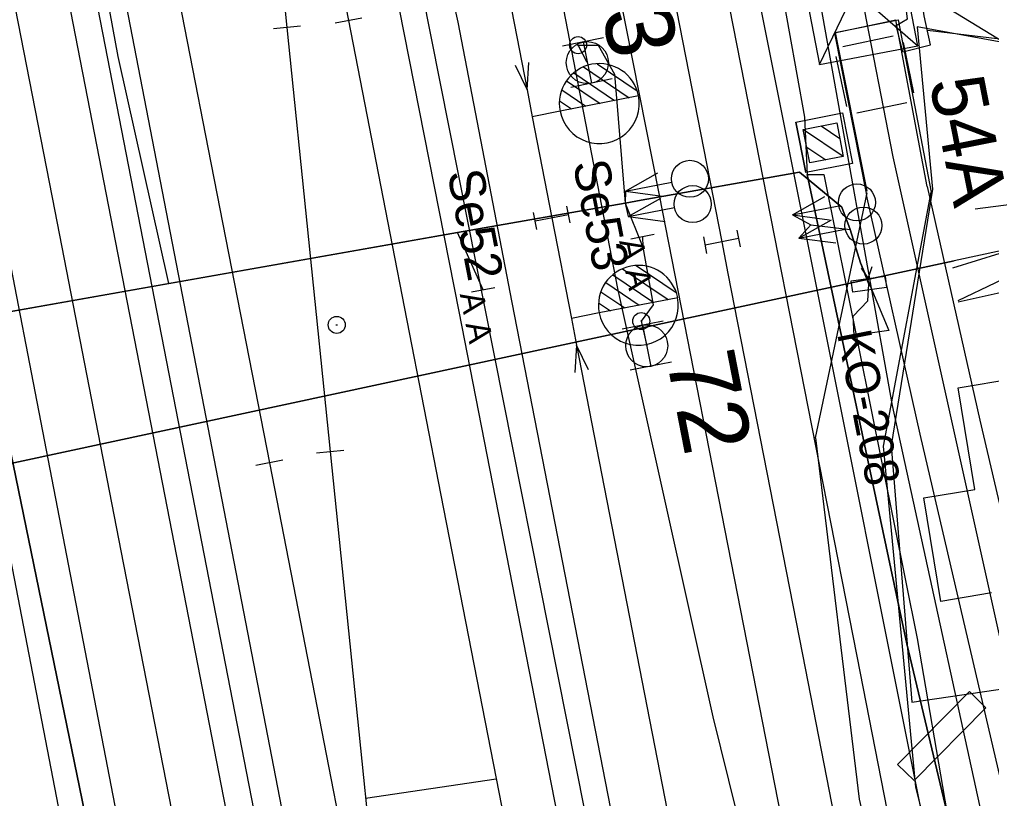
# Model space of a CAD drawing. Extents: x -545736 to -544888, y -1122892 to -1119128.
# Drawn here: x -545268.13 to -545239.66, y -1121503.39 to -1121480.58 of the extents above; entities that cross this region are included whole.
import ezdxf

# ---------------------------------------------------------------- set-up
doc = ezdxf.new("R2010")
doc.units = 0
for name, color, linetype in [('osvětlené plochy-hodnota-obrys', 7, 'Continuous'), ('Vrstva 1 - Koleje', 7, 'Continuous'), ('Vrstva 11 - Trakce', 7, 'Continuous'), ('Vrstva 12 - Trakce zaklady', 7, 'Continuous'), ('Vrstva 16', 7, 'Continuous'), ('Vrstva 16_plochy', 7, 'Continuous'), ('Vrstva 17', 7, 'Continuous'), ('Vrstva 2 - Vyhybky', 7, 'Continuous'), ('Vrstva 23 - PHS - pozemni - schody - eskalatory', 7, 'Continuous'), ('Vrstva 26', 7, 'Continuous'), ('Vrstva 27', 7, 'Continuous'), ('Vrstva 28', 7, 'Continuous'), ('Vrstva 28 - zabzar', 7, 'Continuous'), ('Vrstva 3 - Lisy - Pocitaci body', 7, 'Continuous'), ('Vrstva 31', 7, 'Continuous'), ('Vrstva 33 - prvky sdelzar', 7, 'Continuous'), ('Vrstva 34', 7, 'Continuous'), ('Vrstva 35', 7, 'Continuous'), ('Vrstva 4 - Teren - stezky - prechody - plochy', 7, 'Continuous'), ('Vrstva 44', 7, 'Continuous'), ('Vrstva 49', 7, 'Continuous'), ('Vrstva 51', 7, 'Continuous'), ('Vrstva 6 - Navesti', 7, 'Continuous'), ('Vrstva 63', 7, 'Continuous'), ('Vrstva 7 - Namezniky-vystroj', 7, 'Continuous')]:
    doc.layers.add(name, color=color, linetype=linetype)

msp = doc.modelspace()

# ---------------------------------------------------------------- linework, layer by layer
at = {"layer": 'osvětlené plochy-hodnota-obrys'}
for points in [[(-545242.558, -1121491.884), (-545279.836, -1121284), (-545274.806, -1121164.44), (-545297.02, -1121162.185), (-545335.871, -1121169.76), (-545274.177, -1121498.125)], [(-545225.649, -1121565.547), (-545228.661, -1121555.541), (-545242.558, -1121491.884)]]:
    msp.add_lwpolyline(points, dxfattribs=at)
at = {"layer": 'Vrstva 1 - Koleje'}
for points in [[(-545262.507, -1121410.398), (-545262.372, -1121411.093), (-545261.803, -1121414.016), (-545261.166, -1121417.289), (-545259.554, -1121425.557), (-545257.889, -1121434.106), (-545256.293, -1121442.3), (-545253.813, -1121455.021), (-545252.192, -1121463.347), (-545250.579, -1121471.624), (-545249.065, -1121479.401), (-545247.561, -1121487.089), (-545247.38, -1121488.014), (-545245.2, -1121499.168), (-545243.649, -1121507.124), (-545242.128, -1121514.923), (-545240.701, -1121522.235), (-545239.742, -1121527.165), (-545236.674, -1121542.917), (-545232.9, -1121554.103), (-545232.644, -1121554.861)], [(-545271.831, -1121412.223), (-545270.376, -1121419.688), (-545264.77, -1121438.968), (-545261.284, -1121450.925), (-545255.713, -1121470.07), (-545253.264, -1121482.64), (-545253.111, -1121483.425)], [(-545276.49, -1121413.135), (-545275.337, -1121419.059), (-545273.775, -1121427.064), (-545272.315, -1121434.562), (-545270.926, -1121441.685), (-545269.354, -1121449.751), (-545267.851, -1121457.452), (-545267.665, -1121458.407), (-545265.736, -1121468.305), (-545264.214, -1121476.109), (-545262.603, -1121484.378), (-545260.81, -1121493.562), (-545256.987, -1121513.182), (-545255.196, -1121522.374), (-545254.536, -1121525.758), (-545254.381, -1121526.553)], [(-545262.934, -1121433.025), (-545261.614, -1121439.792), (-545259.539, -1121450.431), (-545255.713, -1121470.07), (-545253.264, -1121482.64), (-545253.111, -1121483.425)], [(-545264.923, -1121447.662), (-545264.772, -1121448.437), (-545262.317, -1121461.012), (-545258.493, -1121480.612), (-545257.28, -1121486.838), (-545255.786, -1121494.509), (-545254.093, -1121503.208), (-545252.404, -1121511.864), (-545250.837, -1121519.906), (-545249.341, -1121527.573), (-545248.751, -1121530.6), (-545248.408, -1121532.36)], [(-545264.923, -1121447.662), (-545264.772, -1121448.437), (-545262.317, -1121461.012), (-545260.294, -1121480.812), (-545259.029, -1121493.226), (-545256.987, -1121513.182), (-545255.196, -1121522.374), (-545254.536, -1121525.758), (-545254.381, -1121526.553)], [(-545272.358, -1121459.202), (-545270.418, -1121469.16), (-545268.418, -1121479.39), (-545267.096, -1121486.195), (-545265.156, -1121496.137), (-545263.098, -1121506.678), (-545261.272, -1121516.035), (-545259.394, -1121525.622), (-545257.684, -1121534.921), (-545257.618, -1121535.277), (-545256.11, -1121545.231), (-545255.449, -1121550.493), (-545254.843, -1121556.163), (-545254.458, -1121560.418), (-545254.146, -1121564.071), (-545253.508, -1121571.471), (-545252.196, -1121587.434), (-545249.323, -1121602.182), (-545249.218, -1121602.722)], [(-545253.111, -1121483.425), (-545252.538, -1121486.383), (-545251.966, -1121489.333)], [(-545251.966, -1121489.333), (-545251.813, -1121490.118), (-545248.787, -1121505.64), (-545243.798, -1121521.586), (-545241.757, -1121527.849), (-545236.674, -1121542.917), (-545232.9, -1121554.103), (-545232.644, -1121554.861)], [(-545251.966, -1121489.333), (-545251.813, -1121490.118), (-545248.787, -1121505.64), (-545245.606, -1121521.941), (-545243.747, -1121531.464)]]:
    msp.add_lwpolyline(points, dxfattribs=at)
at = {"layer": 'Vrstva 11 - Trakce'}
for p, q in [((-545245.172, -1121483.799), (-545244.001, -1121484.584)), ((-545244.653, -1121483.696), (-545244.104, -1121484.064)), ((-545245.073, -1121484.316), (-545244.518, -1121484.689))]:
    msp.add_line(p, q, dxfattribs=at)
msp.add_lwpolyline([(-545244.194, -1121483.606), (-545244.001, -1121484.587), (-545244.982, -1121484.78), (-545245.175, -1121483.799)], close=True, dxfattribs=at)
at = {"layer": 'Vrstva 12 - Trakce zaklady'}
for p, q in [((-545245.396, -1121483.585), (-545244.023, -1121483.314)), ((-545243.731, -1121484.792), (-545245.104, -1121485.063))]:
    msp.add_line(p, q, dxfattribs=at)
for points in [[(-545245.104, -1121485.063), (-545245.396, -1121483.585), (-545244.023, -1121483.314), (-545243.731, -1121484.792), (-545245.104, -1121485.063)], [(-545244.023, -1121483.314), (-545244.023, -1121483.314), (-545243.731, -1121484.792), (-545243.731, -1121484.792)], [(-545245.396, -1121483.585), (-545245.396, -1121483.585), (-545245.104, -1121485.063), (-545245.104, -1121485.063)]]:
    msp.add_lwpolyline(points, dxfattribs=at)
at = {"layer": 'Vrstva 16'}
for p, q in [((-545244.819, -1121492.83), (-545243.304, -1121485.657)), ((-545242.827, -1121493.072), (-545241.429, -1121485.638))]:
    msp.add_line(p, q, dxfattribs=at)
for points in [[(-545244.819, -1121492.83), (-545243.535, -1121503.405), (-545242.594, -1121507.523), (-545242.146, -1121508.542), (-545236.367, -1121515.605), (-545236.148, -1121516.062)], [(-545234.51, -1121515.366), (-545235.05, -1121514.456), (-545240.697, -1121507.522), (-545240.867, -1121507.078), (-545241.875, -1121503.055), (-545242.827, -1121493.072)]]:
    msp.add_lwpolyline(points, dxfattribs=at)
at = {"layer": 'Vrstva 16_plochy'}
msp.add_line((-545242.256, -1121481.525), (-545242.453, -1121480.759), dxfattribs=at)
for points in [[(-545242.453, -1121480.759), (-545242.124, -1121480.556), (-545242.465, -1121477.85), (-545241.84, -1121477.607), (-545242.071, -1121476.407), (-545246.05, -1121477.203), (-545246.055, -1121477.191), (-545246.306, -1121476.097), (-545247.276, -1121471.24), (-545242.26, -1121473.137)], [(-545242.256, -1121481.525), (-545241.45, -1121481.321), (-545241.63, -1121480.47), (-545241.966, -1121478.12), (-545241.235, -1121477.966), (-545241.565, -1121476.301), (-545241.813, -1121475.513)]]:
    msp.add_lwpolyline(points, dxfattribs=at)
at = {"layer": 'Vrstva 17'}
msp.add_line((-545239.108, -1121481.368), (-545247.14, -1121476.462), dxfattribs=at)
at = {"layer": 'Vrstva 2 - Vyhybky'}
for p, q in [((-545258.1, -1121480.536), (-545258.886, -1121480.688)), ((-545259.896, -1121480.771), (-545260.692, -1121480.853)), ((-545251.215, -1121481.873), (-545250.04, -1121482.664)), ((-545251.898, -1121482.145), (-545250.699, -1121482.953)), ((-545251.615, -1121481.969), (-545250.277, -1121482.871)), ((-545252.105, -1121482.372), (-545251.122, -1121483.036)), ((-545249.997, -1121482.816), (-545252.296, -1121483.264)), ((-545252.246, -1121482.643), (-545251.543, -1121483.117)), ((-545249.997, -1121482.816), (-545249.997, -1121482.816)), ((-545252.313, -1121482.965), (-545251.966, -1121483.199)), ((-545252.295, -1121483.264), (-545253.111, -1121483.425)), ((-545250.468, -1121487.879), (-545249.132, -1121488.782)), ((-545250.068, -1121487.782), (-545248.894, -1121488.575)), ((-545250.752, -1121488.054), (-545249.554, -1121488.863)), ((-545250.959, -1121488.281), (-545249.976, -1121488.945)), ((-545248.852, -1121488.727), (-545251.15, -1121489.172)), ((-545251.1, -1121488.552), (-545250.398, -1121489.026)), ((-545248.852, -1121488.726), (-545248.852, -1121488.727)), ((-545251.168, -1121488.874), (-545250.821, -1121489.108)), ((-545251.15, -1121489.172), (-545251.966, -1121489.333)), ((-545259.427, -1121493.267), (-545258.631, -1121493.185)), ((-545260.417, -1121493.485), (-545261.203, -1121493.639))]:
    msp.add_line(p, q, dxfattribs=at)
for points in [[(-545264.923, -1121447.662), (-545264.772, -1121448.437), (-545262.317, -1121461.012), (-545258.493, -1121480.612)], [(-545259.539, -1121450.431), (-545255.713, -1121470.07), (-545253.264, -1121482.64), (-545253.111, -1121483.425)], [(-545262.317, -1121461.012), (-545260.294, -1121480.812)], [(-545253.615, -1121481.921), (-545253.264, -1121482.64), (-545253.209, -1121481.842)], [(-545251.966, -1121489.333), (-545251.813, -1121490.118), (-545248.787, -1121505.64), (-545245.606, -1121521.941)], [(-545251.462, -1121490.837), (-545251.813, -1121490.118), (-545251.868, -1121490.916)], [(-545259.029, -1121493.226), (-545256.987, -1121513.182)], [(-545260.81, -1121493.562), (-545256.987, -1121513.182), (-545254.536, -1121525.758), (-545254.381, -1121526.553)]]:
    msp.add_lwpolyline(points, dxfattribs=at)
for centre, radius, start, end in [((-545251.147, -1121483.04), 1.171, 11.0499, 191.0108), ((-545251.147, -1121483.041), 1.17, 190.9604, 11.4299), ((-545250.002, -1121488.95), 1.171, 10.9996, 190.9604), ((-545250.002, -1121488.951), 1.17, 190.91, 11.3796)]:
    msp.add_arc(centre, radius, start, end, dxfattribs=at)
at = {"layer": 'Vrstva 23 - PHS - pozemni - schody - eskalatory'}
msp.add_lwpolyline([(-545239.825, -1121500.735), (-545240.306, -1121500.26), (-545242.411, -1121502.392), (-545241.931, -1121502.867)], close=True, dxfattribs=at)
at = {"layer": 'Vrstva 26'}
for points in [[(-545097.437, -1122052.623), (-545072.287, -1122039.894), (-545085.621, -1122009.744), (-545089.841, -1121964.946), (-545095.239, -1121958.274), (-545095.745, -1121940.272), (-545098.424, -1121935.947), (-545099.088, -1121910.293), (-545099.581, -1121891.247), (-545095.82, -1121860.673), (-545104.239, -1121857.434), (-545113.591, -1121811.167), (-545113.924, -1121803.223), (-545124.359, -1121753.762), (-545132.104, -1121728.782), (-545141.308, -1121704.806), (-545150.282, -1121669.65), (-545151.919, -1121656.143), (-545151.404, -1121636.531), (-545180.167, -1121637.447), (-545212.798, -1121581.796), (-545235.977, -1121514.184), (-545242.54, -1121484.599), (-545257.211, -1121409.362)], [(-545240.793, -1121487.85), (-545238.719, -1121487.203), (-545240.754, -1121487.641), (-545273.299, -1121494.637), (-545275.897, -1121495.196), (-545278.827, -1121494.413), (-545280.156, -1121493.901), (-545287.156, -1121495.163), (-545287.928, -1121496.789), (-545287, -1121503.852)], [(-545273.299, -1121494.637), (-545240.754, -1121487.641)]]:
    msp.add_lwpolyline(points, dxfattribs=at)
at = {"layer": 'Vrstva 27'}
for p, q in [((-545251.758, -1121481.352), (-545251.782, -1121481.308)), ((-545243.767, -1121488.235), (-545243.765, -1121488.231)), ((-545249.925, -1121489.386), (-545249.915, -1121489.434))]:
    msp.add_line(p, q, dxfattribs=at)
msp.add_lwpolyline([(-545243.482, -1121487.857), (-545243.272, -1121488.165), (-545243.152, -1121487.812)], dxfattribs=at)
msp.add_lwpolyline([(-545243.768, -1121488.232), (-545242.777, -1121488.098), (-545242.732, -1121488.428), (-545243.723, -1121488.562)], close=True, dxfattribs=at)
for centre in [(-545251.77, -1121481.33), (-545249.92, -1121489.41)]:
    msp.add_circle(centre, 0.25, dxfattribs=at)
at = {"layer": 'Vrstva 28'}
msp.add_line((-545258.863, -1121489.522), (-545258.813, -1121489.522), dxfattribs=at)
msp.add_circle((-545258.838, -1121489.522), 0.25, dxfattribs=at)
at = {"layer": 'Vrstva 28 - zabzar'}
for p, q in [((-545244.95, -1121486.59), (-545243.8, -1121486.73)), ((-545254.55, -1121488.49), (-545255.296, -1121486.818)), ((-545249.88, -1121486.93), (-545249.87, -1121487.25))]:
    msp.add_line(p, q, dxfattribs=at)
for points in [[(-545263.754, -1121488.311), (-545265.24, -1121481.66), (-545267.32, -1121470.35), (-545269.76, -1121459.69), (-545270.37, -1121458.69), (-545270.17, -1121457.49)], [(-545251.5, -1121481.84), (-545251.77, -1121481.33), (-545251.18, -1121481.33), (-545250.7, -1121482.18), (-545250.391, -1121485.953)], [(-545260.9, -1121532.21), (-545262.64, -1121521.21), (-545269.213, -1121489.275), (-545263.754, -1121488.311), (-545255.296, -1121486.818), (-545250.391, -1121485.953), (-545249.918, -1121485.869), (-545245.288, -1121485.052)], [(-545242.67, -1121489.69), (-545243.68, -1121489.83), (-545243.71, -1121489.27), (-545243.28, -1121488.82), (-545243.25, -1121488.33), (-545243.5, -1121487.7), (-545243.8, -1121486.73), (-545244.04, -1121486.07), (-545245.288, -1121485.052)], [(-545250.38, -1121485.61), (-545250.391, -1121485.953), (-545250.3, -1121486.35)], [(-545250.391, -1121485.953), (-545249.87, -1121487.25), (-545249.57, -1121488.93), (-545249.92, -1121489.41), (-545249.76, -1121490.13)], [(-545245.49, -1121486.3), (-545244.95, -1121486.59), (-545245.3, -1121486.98)]]:
    msp.add_lwpolyline(points, dxfattribs=at)
at = {"layer": 'Vrstva 3 - Lisy - Pocitaci body'}
for p, q in [((-545251.02, -1121481.113), (-545252.227, -1121481.36)), ((-545251.623, -1121481.236), (-545251.377, -1121482.444)), ((-545250.773, -1121482.32), (-545251.98, -1121482.567)), ((-545250.38, -1121485.61), (-545249.43, -1121485.073)), ((-545250.38, -1121485.61), (-545249.026, -1121485.346)), ((-545250.38, -1121485.61), (-545249.298, -1121485.75)), ((-545250.3, -1121486.35), (-545249.35, -1121485.813)), ((-545245.49, -1121486.3), (-545244.54, -1121485.764)), ((-545252.981, -1121486.724), (-545253.076, -1121486.233)), ((-545252, -1121486.533), (-545252.095, -1121486.042)), ((-545250.3, -1121486.35), (-545248.946, -1121486.086)), ((-545245.49, -1121486.3), (-545244.135, -1121486.036)), ((-545253.029, -1121486.478), (-545252.047, -1121486.288)), ((-545250.3, -1121486.35), (-545249.218, -1121486.49)), ((-545245.49, -1121486.3), (-545244.408, -1121486.441)), ((-545245.3, -1121486.98), (-545244.35, -1121486.443)), ((-545247.118, -1121486.748), (-545247.022, -1121487.238)), ((-545245.3, -1121486.98), (-545243.946, -1121486.716)), ((-545248.1, -1121486.94), (-545248.004, -1121487.43)), ((-545247.07, -1121486.993), (-545248.052, -1121487.185)), ((-545245.3, -1121486.98), (-545244.218, -1121487.12)), ((-545249.273, -1121489.408), (-545250.482, -1121489.643)), ((-545249.878, -1121489.525), (-545249.642, -1121490.735)), ((-545249.038, -1121490.617), (-545250.247, -1121490.852))]:
    msp.add_line(p, q, dxfattribs=at)
for centre, radius in [((-545251.499, -1121481.842), 0.616), ((-545248.493, -1121485.244), 0.542), ((-545248.413, -1121485.984), 0.542), ((-545243.603, -1121485.935), 0.542), ((-545243.413, -1121486.614), 0.542), ((-545249.759, -1121490.132), 0.616)]:
    msp.add_circle(centre, radius, dxfattribs=at)
at = {"layer": 'Vrstva 31'}
for points in [[(-545245.288, -1121485.052), (-545249.918, -1121485.869), (-545250.391, -1121485.953), (-545255.296, -1121486.818), (-545269.213, -1121489.275), (-545274.17, -1121490.15), (-545276.21, -1121490.53), (-545277.51, -1121491.23), (-545280.09, -1121493.53), (-545282.98, -1121493.96), (-545287.42, -1121494.9), (-545288.26, -1121496.38), (-545287.72, -1121499.81), (-545286.73, -1121504.29), (-545285.98, -1121506.49), (-545286.39, -1121506.56)], [(-545245.288, -1121485.052), (-545249.918, -1121485.869), (-545250.391, -1121485.953), (-545255.296, -1121486.818), (-545269.213, -1121489.275), (-545262.64, -1121521.21), (-545260.84, -1121532.54), (-545266.43, -1121533.83), (-545268.66, -1121534.19), (-545269.96, -1121534.64), (-545265.7, -1121552.63), (-545264.92, -1121556.08), (-545263.22, -1121565.23), (-545260.72, -1121578.26), (-545257.95, -1121591.89), (-545254.58, -1121607.83), (-545254.47, -1121613.22), (-545255.28, -1121613.53), (-545259.51, -1121614.69), (-545260.17, -1121614.97), (-545261.24, -1121612.78), (-545262.15, -1121612.31), (-545262.45, -1121611.58)], [(-545245.288, -1121485.052), (-545244.04, -1121486.07), (-545243.8, -1121486.73), (-545243.5, -1121487.7), (-545242.67, -1121489.69)], [(-545245.288, -1121485.052), (-545244.04, -1121486.07), (-545243.8, -1121486.73), (-545243.5, -1121487.7), (-545242.67, -1121489.69)], [(-545240.638, -1121488.806), (-545238.428, -1121487.752), (-545227.164, -1121492.751), (-545226.347, -1121492.096)], [(-545226.347, -1121492.096), (-545227.164, -1121492.801), (-545238.177, -1121488.314), (-545240.638, -1121488.856)]]:
    msp.add_lwpolyline(points, dxfattribs=at)
at = {"layer": 'Vrstva 33 - prvky sdelzar'}
msp.add_lwpolyline([(-545245.288, -1121485.052), (-545249.918, -1121485.869), (-545250.391, -1121485.953), (-545255.296, -1121486.818), (-545269.213, -1121489.275), (-545274.17, -1121490.15)], dxfattribs=at)
at = {"layer": 'Vrstva 34'}
for p, q in [((-545244.013, -1121481.367), (-545242.545, -1121481.061)), ((-545242.249, -1121481.255), (-545241.943, -1121482.723)), ((-545243.901, -1121483.131), (-545244.207, -1121481.663)), ((-545242.137, -1121483.019), (-545243.605, -1121483.325))]:
    msp.add_line(p, q, dxfattribs=at)
for points in [[(-545243.668, -1121479.739), (-545241.819, -1121481.355), (-545253.781, -1121419.374), (-545254.848, -1121421.672), (-545256.694, -1121419.914), (-545244.697, -1121481.898), (-545241.819, -1121481.355)], [(-545244.697, -1121481.898), (-545243.668, -1121479.739), (-545254.848, -1121421.672)]]:
    msp.add_lwpolyline(points, dxfattribs=at)
at = {"layer": 'Vrstva 35'}
msp.add_line((-545269.213, -1121489.275), (-545263.754, -1121488.311), dxfattribs=at)
for points in [[(-545242.463, -1121480.602), (-545244.257, -1121480.975), (-545243.32, -1121485.713)], [(-545241.541, -1121485.465), (-545242.463, -1121480.602)], [(-545263.754, -1121488.311), (-545255.296, -1121486.818), (-545250.391, -1121485.953), (-545249.918, -1121485.869), (-545245.288, -1121485.052)], [(-545241.541, -1121485.465), (-545239.999, -1121492.308), (-545237.251, -1121504.071), (-545235.337, -1121513.168), (-545234.596, -1121515.041), (-545224.398, -1121544.845), (-545211.981, -1121581.286), (-545198.438, -1121604.211), (-545181.421, -1121633.25), (-545182.966, -1121634.194), (-545200.042, -1121605.172), (-545213.729, -1121581.837), (-545226.104, -1121545.417), (-545236.204, -1121516.019), (-545237.061, -1121513.796), (-545239.019, -1121504.439), (-545241.749, -1121492.723), (-545243.32, -1121485.713)]]:
    msp.add_lwpolyline(points, dxfattribs=at)
at = {"layer": 'Vrstva 4 - Teren - stezky - prechody - plochy'}
for points in [[(-545259.454, -1121409.801), (-545256.779, -1121423.634), (-545256.524, -1121424.828), (-545256.645, -1121424.859), (-545246.388, -1121477.246), (-545246.041, -1121478.436), (-545245.134, -1121483.441), (-545245.058, -1121485.118), (-545242.142, -1121498.86), (-545240.965, -1121503.781), (-545240.592, -1121505.558), (-545236.724, -1121527.376), (-545236.317, -1121528.858), (-545234.837, -1121535.705), (-545233.269, -1121542.92), (-545231.754, -1121547.059), (-545231.433, -1121548.349)], [(-545261.031, -1121410.109), (-545252.885, -1121451.66), (-545247.894, -1121477.411), (-545243.606, -1121499.217), (-545237.682, -1121529.497), (-545236.332, -1121535.818), (-545234.439, -1121543.527)], [(-545244.448, -1121510.946), (-545249.383, -1121485.722), (-545256.971, -1121447.411), (-545260.809, -1121427.087), (-545263.937, -1121410.678)], [(-545244.448, -1121510.946), (-545245.318, -1121511.096), (-545247.814, -1121501), (-545250.603, -1121488.46), (-545258.764, -1121446.291), (-545261.879, -1121430.313), (-545263.872, -1121418.434), (-545264.945, -1121410.876)], [(-545278.006, -1121413.432), (-545276.701, -1121420.101), (-545267.383, -1121467.848), (-545259.234, -1121509.979), (-545254.666, -1121533.136), (-545253.23, -1121541.319), (-545251.944, -1121549.565), (-545250.687, -1121560.647), (-545249.635, -1121574.047), (-545248.988, -1121585.208), (-545248.342, -1121594.545), (-545249.227, -1121594.662)], [(-545279.681, -1121413.76), (-545278.377, -1121420.495), (-545269.048, -1121467.98), (-545260.773, -1121510.451), (-545257.559, -1121527.04), (-545255.905, -1121536.357), (-545255.137, -1121541.48), (-545254, -1121550.011), (-545252.97, -1121560.288), (-545251.62, -1121574.982), (-545250.507, -1121585.208), (-545249.227, -1121594.662)], [(-545282.645, -1121414.34), (-545281.11, -1121422.206), (-545272.131, -1121468.459), (-545263.928, -1121510.887), (-545260.8, -1121526.502), (-545258.835, -1121537.261), (-545257.723, -1121545.019), (-545256.998, -1121549.941), (-545257.952, -1121550.162)], [(-545284.339, -1121414.671), (-545282.857, -1121422.297), (-545273.734, -1121468.765), (-545265.544, -1121511.16), (-545260.299, -1121537.903), (-545257.952, -1121550.162)], [(-545240.505, -1121561.147), (-545239.566, -1121560.896), (-545245.228, -1121532.163), (-545247.635, -1121519.972), (-545253.7, -1121488.87), (-545255.277, -1121480.656), (-545257.548, -1121470.499), (-545259.747, -1121461.545), (-545260.646, -1121461.771)], [(-545240.505, -1121561.147), (-545243.401, -1121548.243), (-545246.366, -1121534.665), (-545249.088, -1121520.658), (-545255.256, -1121489.13), (-545260.646, -1121461.771)], [(-545240.965, -1121503.781), (-545242.142, -1121498.86), (-545245.058, -1121485.118), (-545244.569, -1121485.122), (-545241.843, -1121498.706), (-545240.965, -1121503.781), (-545240.592, -1121505.558)]]:
    msp.add_lwpolyline(points, dxfattribs=at)
at = {"layer": 'Vrstva 44'}
for points in [[(-545267.427, -1121472.082), (-545256.228, -1121529.649), (-545256.214, -1121529.964)], [(-545257.662, -1121473.102), (-545246.805, -1121527.781), (-545246.74, -1121528.11), (-545246.74, -1121528.11), (-545246.443, -1121528.009), (-545237.671, -1121526.196), (-545237.454, -1121526.207)], [(-545246.746, -1121478.609), (-545239.985, -1121512.465), (-545239.309, -1121513.378)]]:
    msp.add_lwpolyline(points, dxfattribs=at)
at = {"layer": 'Vrstva 49'}
for p, q in [((-545244.236, -1121480.955), (-545242.397, -1121480.585)), ((-545242.397, -1121480.585), (-545241.429, -1121485.638)), ((-545244.236, -1121480.955), (-545243.313, -1121485.609))]:
    msp.add_line(p, q, dxfattribs=at)
msp.add_lwpolyline([(-545241.54, -1121480.896), (-545239.493, -1121481.139), (-545231.775, -1121483.569), (-545221.13, -1121485.174)], dxfattribs=at)
at = {"layer": 'Vrstva 51'}
for p, q in [((-545211.449, -1121486.334), (-545241.836, -1121480.794)), ((-545241.836, -1121480.794), (-545241.394, -1121485.544)), ((-545241.394, -1121485.544), (-545242.602, -1121493.053)), ((-545240.64, -1121491.36), (-545234.23, -1121490.31)), ((-545240.15, -1121494.34), (-545240.64, -1121491.36)), ((-545242.602, -1121493.053), (-545241.992, -1121500.564)), ((-545241.64, -1121494.59), (-545240.15, -1121494.34)), ((-545241.15, -1121497.62), (-545241.64, -1121494.59)), ((-545239.66, -1121497.37), (-545241.15, -1121497.62)), ((-545241.992, -1121500.564), (-545239.199, -1121500.154))]:
    msp.add_line(p, q, dxfattribs=at)
at = {"layer": 'Vrstva 6 - Navesti'}
for p, q in [((-545250.223, -1121486.998), (-545249.537, -1121486.862)), ((-545254.894, -1121488.557), (-545254.206, -1121488.423))]:
    msp.add_line(p, q, dxfattribs=at)
at = {"layer": 'Vrstva 63'}
msp.add_line((-545201.218, -1121481.101), (-545240.141, -1121486.132), dxfattribs=at)
at = {"layer": 'Vrstva 7 - Namezniky-vystroj'}
msp.add_line((-545257.99, -1121503.379), (-545254.17, -1121502.813), dxfattribs=at)

# ---------------------------------------------------------------- texts
at = {"layer": 'Vrstva 11 - Trakce'}
msp.add_text('54A', height=1.6, rotation=281.1757, dxfattribs=at).set_placement((-545241.487, -1121482.396))
at = {"layer": 'Vrstva 2 - Vyhybky'}
for s, rotation, p in [('73', 281.0304, (-545251.357, -1121478.889)), ('72', 281.0345, (-545249.19, -1121490.489))]:
    msp.add_text(s, height=2, rotation=rotation, dxfattribs=at).set_placement(p)
at = {"layer": 'Vrstva 27'}
msp.add_text('KO-208', height=1, rotation=281.0588, dxfattribs=at).set_placement((-545244.188, -1121489.77))
at = {"layer": 'Vrstva 6 - Navesti'}
for s, height, rotation, p in [('Se53', 1.05, 281.0403, (-545251.925, -1121484.786)), ('Se52', 1.05, 281.0441, (-545255.602, -1121485.069)), ('A A ', 0.7, 281.2144, (-545250.567, -1121487.066)), ('A A ', 0.7, 281.0301, (-545255.237, -1121488.624))]:
    msp.add_text(s, height=height, rotation=rotation, dxfattribs=at).set_placement(p)

doc.saveas('drawing.dxf')
